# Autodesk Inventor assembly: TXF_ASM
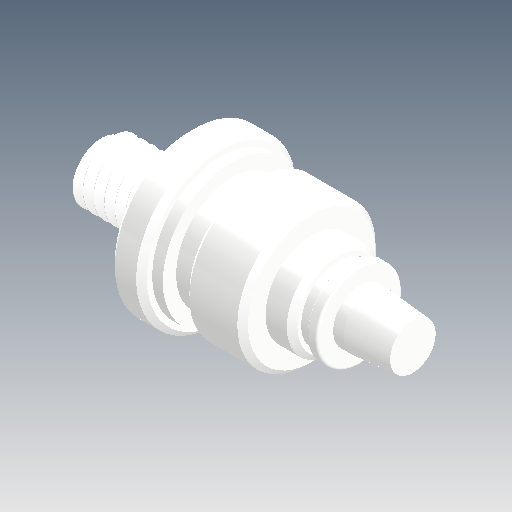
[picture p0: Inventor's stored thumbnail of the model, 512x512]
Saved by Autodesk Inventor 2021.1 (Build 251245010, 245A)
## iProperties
Created: 2021-05
Part Number: TXF_ASM
Document SubType Name: Assembly
Designer: user
Author: user
Revision Number: ÈÎºÎ
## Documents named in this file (3)
- D:\Vault_2016\Projekty\Clamptek\Hydraulic\CHLC\CHLC-32\Inventor\CHLC-MF32\TXF_ASM.iam
- D:\Vault_2016\Projekty\Clamptek\Hydraulic\CHLC\CHLC-32\Inventor\CHLC-MF32\TXF-02.ipt
- D:\Vault_2016\Projekty\Clamptek\Hydraulic\CHLC\CHLC-32\Inventor\CHLC-MF32\TSF-01.ipt
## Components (2 placed, 2 different names)
1. TXF-02_21
2. TSF-01_22
